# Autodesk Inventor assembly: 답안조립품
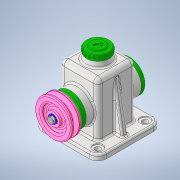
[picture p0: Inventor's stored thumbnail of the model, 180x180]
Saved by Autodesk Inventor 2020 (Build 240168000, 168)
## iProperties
Created: 2021-07
Part Number: 답안조립품
Document SubType Name: Assembly
Designer: Owner
Author: Owner
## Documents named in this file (14)
- C:\Users\Owner\Desktop\710715V1010\답안조립품.iam
- C:\Users\Owner\Desktop\710715V1010\본체.ipt
- C:\Users\Owner\Desktop\710715V1010\V-벨트풀리.ipt
- C:\Users\Owner\Desktop\710715V1010\뒤커버.ipt
- C:\Users\Owner\Desktop\710715V1010\멈춤링 15 x 1.ipt
- C:\Users\Owner\Desktop\710715V1010\베어링 15 x 35 x 11.ipt
- C:\Users\Owner\Desktop\710715V1010\볼트 M4 x 10.ipt
- C:\Users\Owner\Desktop\710715V1010\볼트 M6 x 12.ipt
- C:\Users\Owner\Desktop\710715V1010\상부캡.ipt
- C:\Users\Owner\Desktop\710715V1010\앞커버.ipt
- C:\Users\Owner\Desktop\710715V1010\오일실 15 25 7.ipt
- C:\Users\Owner\Desktop\710715V1010\와셔.ipt
- C:\Users\Owner\Desktop\710715V1010\축.ipt
- C:\Users\Owner\Desktop\710715V1010\키 5 x 5 x 14.ipt
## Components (1 placed, 1 different names)
1. V-벨트풀리:1
